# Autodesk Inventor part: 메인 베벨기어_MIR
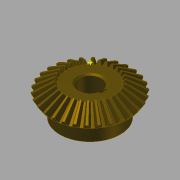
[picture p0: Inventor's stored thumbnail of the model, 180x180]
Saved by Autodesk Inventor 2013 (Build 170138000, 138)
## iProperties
Created: 2014-10
Part Number: 메인 베벨기어_MIR
Material: 강철, 탄소
Document SubType Name: Modeling
Designer: Administrator
Categories: <?xml version="1.0" encoding="UTF-16"?> <MemberInstance><Categories><FamilyTemplate><FamilyTemplateParameter ValueType="xs:double" Id="1" ObjectReferenceKey="da
Mass: 269.926 g
Surface Area: 108.837 cm^2
Volume: 34.2981 cm^3
Density: 7.87 g/cm^3
Author: SeoGD™ [www.esajin.kr]
Revision Number: 1
da_b: 14.400 mm
da_de: 60.000 mm
da_dae: 62.219 mm
da_dfe: 57.337 mm
da_le: 36.056 mm
da_omega: 90.00 deg
da_beta: 0.00 deg
da_delta: 56.31 deg
da_alpha: 20.00 deg
da_he: 4.400 mm
da_ve: 18.336 mm
da_z: 30.000 ul
da_z2: 20.000 ul
fd_dv: 108.167 mm
fd_dva: 112.167 mm
fd_dvb: 101.643 mm
da_zv: 54.083 ul
fd_loft: 14.620 mm
fd_ratio: 0.596 ul
fd_rr: 19.188 mm
fd_angle: 1.68 deg
fd_x1: 1.588 mm
fd_y1: 54.060 mm
fd_x2: 17.869 mm
fd_y2: 6.991 mm
fd_x: 19.457 mm
fd_y: 47.069 mm
fd_angle2: 19.68 deg
fd_dd: 108.647 mm
da_dvw: 108.167 mm
da_dm: 48.018 mm
da_x: 0.000 ul
da_m: 2.000 mm
da_teethtype: 0.000 ul
d56: 10.373 mm
d0: 60.000 mm
d1: 57.337 mm
d2: 62.219 mm
d3: 14.400 mm
d4: 18.336 mm
d7: 19.188 mm
d8: 19.457 mm
d9: 47.069 mm
d11: 14.620 mm
d12: 11.427 mm
d15: 11.587 mm
d16: 28.030 mm
d17: 0.000 ul
d18: 90.00 deg
d19: 0.000 ul
d20: 90.00 deg
d21: 30.000 ul
d22: 360.00 deg
d26: 229.906 mm
d27: 8.110 mm
d28: 60.000 mm
d29: -56.31 deg
d30: 11.427 mm
d31: 11.587 mm
d32: 28.030 mm
d35: 0.000 ul
d37: 0.000 ul
d39: 0.000 ul
d40: 90.00 deg
d41: 30.000 ul
d42: 360.00 deg
d48: 0.000 mm
d49: 0.000 mm
d50: 90.00 deg
d51: 6.00 deg
d52: 0.000 mm
d53: 0.000 mm
d54: 0.00 deg
d57: 57.403 mm
d58: 51.155 mm
d59: 34.184 mm
d60: 30.464 mm
d61: 34.184 mm
d62: 30.464 mm
d65: 229.906 mm
d66: 3.150 ul
d67: 60.000 mm
d68: -56.31 deg
d69: 8.110 mm
d70: 11.587 mm
d71: 28.030 mm
d72: 11.427 mm
d73: 30.464 mm
d74: 34.184 mm
d75: 0.000 ul
d77: 0.000 ul
d79: 0.000 ul
d80: 90.00 deg
d81: 30.000 ul
d82: 360.00 deg
d84: 1.000 ul
d85: 2.000 ul
d86: 2.000 ul
d87: 1.000 ul
d88: 0.000 ul
d89: 0.000 ul
d90: 90.00 deg
d91: 90.00 deg
d92: 90.00 deg
d93: 90.00 deg
d94: 45.000 mm
d95: 13.000 mm
d96: 0.00 deg
d97: 17.000 mm
d104: 5.000 mm
d107: 0.00 deg
d108: 1.000 mm
d111: 2.000 mm
d112: 19.300 mm
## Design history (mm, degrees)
node "메인 베벨 기어"
  sketch "톱니 본체 스케치"
    geometry: L1 (0, -20)-(-31.109, -20) reference; L2 (0, 0)-(-28.669, -21.997) reference; L3 (-28.669, -21.997)-(-31.109, -18.336) reference; L4 (-31.109, -18.336)-(0, 0) reference; L5 (-30, -20)-(0, 0) reference; L6 (-17.219, -13.212)-(-18.685, -11.013) reference; L7 (-28.669, -21.997)-(-17.219, -13.212) reference; L8 (-31.109, -18.336)-(-18.685, -11.013) reference; L9 (0, -39.387)-(0, 6.564) reference
  sketch "시작 스케치"
    geometry: L1 (0, -23.505)-(0, 10.645) reference; L2 (0.709, -2.928)-(-0.709, -2.928) reference; A1 r 57.403 centre (0, -54.083) between (3.232, 3.229) and (-3.232, 3.229) reference; A2 r 19.188 centre (19.457, -7.014) between (3.232, 3.229) and (0.709, -2.928) reference; A3 r 19.188 centre (-19.457, -7.014) between (-0.709, -2.928) and (-3.232, 3.229) reference; 1 further point
  sketch "끝 스케치"
    geometry: L1 (0, -15.359)-(0, 6.983) reference; L2 (0.422, -1.69)-(-0.422, -1.69) reference; A1 r 34.184 centre (0, -32.153) between (1.925, 1.977) and (-1.925, 1.977) reference; A2 r 11.427 centre (11.587, -4.123) between (1.925, 1.977) and (0.422, -1.69) reference; A3 r 11.427 centre (-11.587, -4.123) between (-0.422, -1.69) and (-1.925, 1.977) reference; 1 further point
  sketch "끝 스케치 오른쪽"
    geometry: L1 (0, -41.54)-(0, 13.178) reference; L2 (0.422, -1.69)-(-0.422, -1.69) reference; A1 r 11.427 centre (11.587, -4.123) between (1.925, 1.977) and (0.422, -1.69) reference; A2 r 11.427 centre (-11.587, -4.123) between (-0.422, -1.69) and (-1.925, 1.977) reference; A3 r 34.184 centre (0, -32.153) between (1.925, 1.977) and (-1.925, 1.977) reference; 1 further point
  sketch "끝 스케치 왼쪽"
    geometry: L1 (0, -43.753)-(0, 15.405) reference; L2 (0.422, -1.678)-(-0.422, -1.678) reference; A1 r 34.184 centre (0, -32.142) between (1.925, 1.988) and (-1.925, 1.988) reference; A2 r 11.427 centre (11.587, -4.111) between (1.925, 1.988) and (0.422, -1.678) reference; A3 r 11.427 centre (-11.587, -4.111) between (-0.422, -1.678) and (-1.925, 1.988) reference; 2 further points; 1 other entity
    constraints: 1 other
  sketch "본체 스케치"
    geometry: L1 (0, -35.038)-(0, -19.531) reference; L2 (-28.669, -21.997)-(-17.219, -13.212) reference; L3 (-17.219, -13.212)-(0, -13.212) reference; L4 (-28.669, -21.997)-(0, -21.997) reference
  sketch "Sketch6"
    geometry: L1 (-30, -20)-(0, 0) reference; L2 (0, -37.8)-(0, 6.3) reference
  sketch "스케치8"
    geometry: C1 r 22.5 at (0, 0) reference; 1 further point
  sketch "스케치9"
    geometry: 1 further point
  sketch "스케치10"
    geometry: L1 (-10.8, -2.5)-(-8.124, -2.5) reference; L2 (-8.124, 2.5)-(-10.8, 2.5) reference; L3 (-10.8, 2.5)-(-10.8, -2.5) reference; A1 r 8.5 centre (0, 0) between (-8.124, 2.5) and (-8.124, -2.5) reference; 1 further point
  sketch "3D 스케치 오른쪽"
  sketch "3D 스케치 왼쪽"
  node "메쉬 평면"
  node "맨 위 평면"
  node "톱니 평면"
  node "끝 평면"
  node "끝 평면 왼쪽"
  node "메쉬 평면2"
  node "끝 평면 오른쪽"
  node "Z Axis_1"
  node "맨 위 점"
  node "시작점"
  node "끝점"
feature "Solid1::메인 베벨 기어"
tag "피쳐 태그1"
node "곡면1"
node "솔리드1"
feature "Srf1::파생"
other parameters: "d0" = 10, "da_b" = 14.4, "da_de" = 60, "da_dae" = 62.2188, "da_dfe" = 57.33744, "da_le" = 36.05551, "da_omega" = 90 deg, "da_beta" = 0 deg, "da_delta" = 56.3099 deg, "da_alpha" = 20 deg, "da_he" = 4.4, "da_ve" = 18.3359, "da_z" = 30, "da_z2" = 20, "fd_dv" = 108.16654, "fd_dva" = 112.16654, "fd_dvb" = 101.6433, "da_zv" = 54.0833, "fd_loft" = 14.62, "fd_ratio" = 0.595514, "fd_rr" = 19.18795, "fd_angle" = 1.68259 deg, "fd_x1" = 1.58802, "fd_y1" = 54.05995, "fd_x2" = 17.8691, "fd_y2" = 6.9909, "fd_x" = 19.45712, "fd_y" = 47.06905, "fd_angle2" = 19.6843 deg, "fd_dd" = 108.64654, "da_dvw" = 108.16654, "da_dm" = 48.01848, "da_x" = 0, "da_m" = 2, "da_teethtype" = 0, "d56" = 10.3728, "d1" = 57.33744, "d2" = 62.2188, "d3" = 14.4, "d4" = 18.3359, "d7" = 19.18795, "d8" = 19.45712, "d9" = 47.06905, "d11" = 14.62, "d12" = 11.4267, "d15" = 11.58699, "d16" = 28.03028, "d17" = 0, "d18" = 90 deg, "d19" = 0, "d20" = 90 deg, "d21" = 30, "d22" = 360 deg, "d26" = 229.90621, "d27" = 8.10972, "d28" = 60, "d29" = -56.3099 deg, "d30" = 11.4267, "d31" = 11.58699, "d32" = 28.03028, "d35" = 0, "d37" = 0, "d39" = 0, "d40" = 90 deg, "d41" = 30, "d42" = 360 deg, "d48" = 0, "d49" = 0, "d50" = 90 deg, "d51" = 6 deg, "d52" = 0, "d53" = 0, "d54" = 0 deg, "d57" = 57.40327, "d58" = 51.15527, "d59" = 34.18446, "d60" = 30.46369, "d61" = 34.18446, "d62" = 30.46369, "d65" = 229.90621, "d66" = 3.15, "d67" = 60, "d68" = -56.3099 deg, "d69" = 8.10972, "d70" = 11.58699, "d71" = 28.03028, "d72" = 11.4267, "d73" = 30.46369, "d74" = 34.18446, "d75" = 0, "d77" = 0, "d79" = 0, "d80" = 90 deg, "d81" = 30, "d82" = 360 deg, "d84" = 1, "d85" = 2, "d86" = 2, "d87" = 1, "d88" = 0, "d89" = 0, "d90" = 90 deg, "d91" = 90 deg, "d92" = 90 deg, "d93" = 90 deg, "d94" = 45, "d95" = 13, "d96" = 0 deg, "d97" = 17, "d104" = 5, "d107" = 0 deg, "d108" = 1, "d111" = 2, "d112" = 19.3
